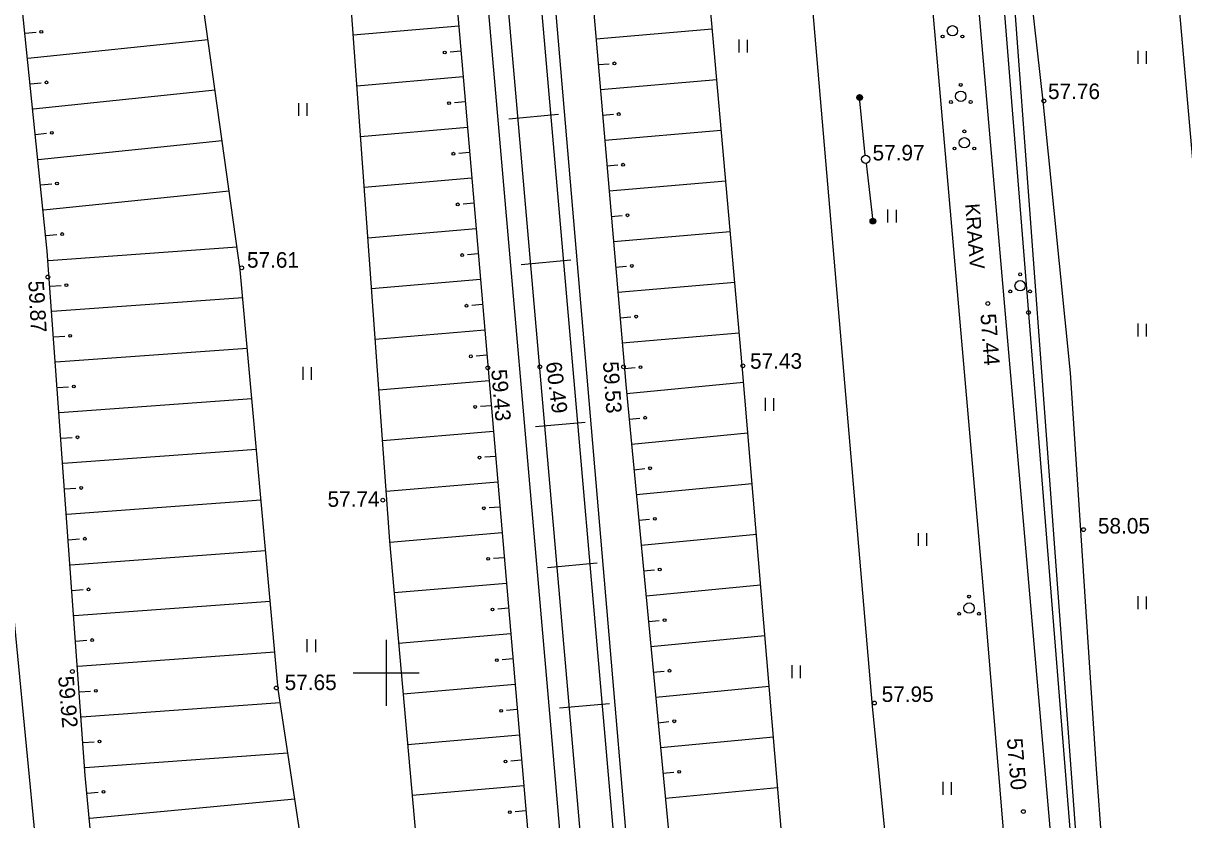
# Model space of a CAD drawing. Extents: x 9156 to 9809, y 2728 to 4000.
# Drawn here: x 9282.5 to 9338.5, y 3542.9 to 3581.3 of the extents above; entities that cross this region are included whole.
import ezdxf

# ---------------------------------------------------------------- set-up
doc = ezdxf.new("R2010")
doc.units = 0
for name, color, linetype in [('Level 1', 7, 'Continuous'), ('Level 54', 7, 'Continuous'), ('Level 58', 7, 'Continuous'), ('Level 6', 7, 'Continuous'), ('Level 7', 7, 'Continuous')]:
    doc.layers.add(name, color=color, linetype=linetype)

# ---------------------------------------------------------------- blocks, each defined once
blk = doc.blocks.new('KKOL')
at = {"layer": 'Level 58'}
for p, q in [((0, 1.59349), (0, -1.5935)), ((-1.5935, 0), (1.59349, 0))]:
    blk.add_line(p, q, dxfattribs=at)

msp = doc.modelspace()

# ---------------------------------------------------------------- linework, layer by layer
at = {"layer": 'Level 1'}
msp.add_line((9347.38, 3362.85), (9317.65, 3734.12), dxfattribs=at)
msp.add_line((9347.38, 3362.85), (9317.65, 3734.12), dxfattribs=at)
at = {"layer": 'Level 54'}
for p, q in [((9330.133, 3591.538), (9331.678, 3577.558)), ((9307.95, 3547.291), (9304.523, 3586.699)), ((9282.578, 3580.836), (9283.101, 3580.89)), ((9298.4, 3580.754), (9303.496, 3581.193)), ((9315.734, 3581.03), (9310.124, 3580.547)), ((9291.401, 3580.516), (9282.704, 3579.617)), ((9317.007, 3580.53), (9317.007, 3579.91)), ((9317.413, 3580.519), (9317.413, 3579.91)), ((9303.601, 3579.972), (9303.077, 3579.927)), ((9336.272, 3579.99), (9336.272, 3579.37)), ((9336.677, 3579.979), (9336.677, 3579.37)), ((9310.229, 3579.326), (9310.753, 3579.371)), ((9298.576, 3578.309), (9303.706, 3578.751)), ((9315.951, 3578.588), (9310.334, 3578.105)), ((9282.83, 3578.398), (9283.353, 3578.452)), ((9291.741, 3578.087), (9282.956, 3577.179)), ((9295.766, 3577.474), (9295.766, 3576.854)), ((9296.171, 3577.462), (9296.171, 3576.854)), ((9303.811, 3577.53), (9303.287, 3577.485)), ((9323.115, 3574.958), (9322.843, 3577.744)), ((9331.678, 3577.558), (9332.995, 3564.459)), ((9305.92, 3576.715), (9308.319, 3576.932)), ((9310.439, 3576.884), (9310.963, 3576.929)), ((9283.082, 3575.96), (9283.605, 3576.014)), ((9298.753, 3575.866), (9303.916, 3576.308)), ((9316.167, 3576.147), (9310.544, 3575.663)), ((9292.081, 3575.658), (9283.208, 3574.741)), ((9304.02, 3575.087), (9303.496, 3575.042)), ((9310.649, 3574.442), (9311.173, 3574.487)), ((9323.158, 3574.56), (9323.481, 3571.779)), ((9283.334, 3573.522), (9283.857, 3573.576)), ((9298.929, 3573.421), (9304.125, 3573.866)), ((9316.384, 3573.705), (9310.754, 3573.221)), ((9292.421, 3573.229), (9283.46, 3572.303)), ((9304.23, 3572.645), (9303.706, 3572.6)), ((9310.859, 3571.999), (9311.383, 3572.045)), ((9324.193, 3572.336), (9324.193, 3571.716)), ((9324.599, 3572.325), (9324.599, 3571.716)), ((9299.106, 3570.976), (9304.334, 3571.424)), ((9283.586, 3571.084), (9284.109, 3571.138)), ((9316.601, 3571.263), (9310.965, 3570.778)), ((9292.8, 3570.523), (9283.698, 3569.863)), ((9304.439, 3570.203), (9303.915, 3570.158)), ((9306.508, 3569.688), (9308.907, 3569.906)), ((9311.07, 3569.557), (9311.593, 3569.602)), ((9284.599, 3526.285), (9280.477, 3568.73)), ((9283.787, 3568.641), (9284.311, 3568.679)), ((9299.283, 3568.531), (9304.543, 3568.982)), ((9316.817, 3568.822), (9311.175, 3568.336)), ((9293.074, 3568.086), (9283.875, 3567.419)), ((9304.648, 3567.761), (9304.124, 3567.716)), ((9311.28, 3567.115), (9311.804, 3567.16)), ((9336.272, 3566.839), (9336.272, 3566.219)), ((9336.677, 3566.828), (9336.677, 3566.219)), ((9299.459, 3566.086), (9304.753, 3566.54)), ((9317.034, 3566.38), (9311.385, 3565.894)), ((9283.964, 3566.196), (9284.488, 3566.234)), ((9293.296, 3565.644), (9284.052, 3564.974)), ((9304.857, 3565.319), (9304.333, 3565.274)), ((9295.969, 3564.75), (9295.969, 3564.13)), ((9296.375, 3564.739), (9296.375, 3564.13)), ((9311.49, 3564.673), (9312.014, 3564.718)), ((9299.636, 3563.641), (9304.962, 3564.098)), ((9332.995, 3564.459), (9334.253, 3545.358)), ((9284.141, 3563.751), (9284.666, 3563.79)), ((9317.242, 3563.993), (9311.599, 3563.452)), ((9293.517, 3563.203), (9284.23, 3562.529)), ((9318.287, 3563.253), (9318.287, 3562.633)), ((9318.692, 3563.242), (9318.692, 3562.633)), ((9305.067, 3562.876), (9304.543, 3562.832)), ((9307.194, 3561.873), (9309.593, 3562.091)), ((9311.716, 3562.232), (9312.24, 3562.283)), ((9284.318, 3561.307), (9284.843, 3561.345)), ((9299.813, 3561.196), (9305.171, 3561.655)), ((9317.448, 3561.551), (9311.833, 3561.013)), ((9293.738, 3560.761), (9284.407, 3560.084)), ((9305.276, 3560.434), (9304.752, 3560.389)), ((9311.95, 3559.793), (9312.474, 3559.843)), ((9299.989, 3558.751), (9305.381, 3559.213)), ((9317.653, 3559.108), (9312.067, 3558.573)), ((9284.496, 3558.862), (9285.02, 3558.9)), ((9293.96, 3558.32), (9284.584, 3557.64)), ((9305.485, 3557.992), (9304.961, 3557.947)), ((9312.184, 3557.353), (9312.708, 3557.403)), ((9300.167, 3556.306), (9305.59, 3556.771)), ((9325.67, 3556.737), (9325.67, 3556.117)), ((9326.076, 3556.725), (9326.076, 3556.117)), ((9284.673, 3556.417), (9285.197, 3556.455)), ((9317.859, 3556.665), (9312.301, 3556.133)), ((9294.181, 3555.878), (9284.762, 3555.195)), ((9305.694, 3555.55), (9305.171, 3555.505)), ((9307.779, 3555.084), (9310.178, 3555.302)), ((9312.418, 3554.913), (9312.942, 3554.963)), ((9284.85, 3553.973), (9285.375, 3554.011)), ((9300.383, 3553.865), (9305.799, 3554.329)), ((9318.065, 3554.223), (9312.535, 3553.693)), ((9294.402, 3553.436), (9284.939, 3552.75)), ((9336.272, 3553.688), (9336.272, 3553.068)), ((9336.677, 3553.676), (9336.677, 3553.068)), ((9305.904, 3553.108), (9305.38, 3553.063)), ((9312.652, 3552.473), (9313.175, 3552.523)), ((9300.599, 3551.423), (9306.008, 3551.887)), ((9318.27, 3551.78), (9312.769, 3551.253)), ((9285.028, 3551.528), (9285.552, 3551.566)), ((9296.173, 3551.613), (9296.173, 3550.993)), ((9296.579, 3551.602), (9296.579, 3550.993)), ((9300, 3551.25), (9300, 3548.75)), ((9294.624, 3550.995), (9285.116, 3550.306)), ((9306.113, 3550.665), (9305.589, 3550.621)), ((9298.75, 3550), (9301.25, 3550)), ((9312.886, 3550.033), (9313.409, 3550.083)), ((9319.566, 3550.363), (9319.566, 3549.743)), ((9319.971, 3550.351), (9319.971, 3549.743)), ((9300.814, 3548.981), (9306.218, 3549.444)), ((9285.205, 3549.083), (9285.729, 3549.121)), ((9318.476, 3549.337), (9313.003, 3548.813)), ((9294.885, 3548.556), (9285.293, 3547.861)), ((9308.367, 3548.303), (9310.766, 3548.521)), ((9306.322, 3548.223), (9305.798, 3548.178)), ((9310.347, 3519.383), (9307.95, 3547.291)), ((9313.12, 3547.593), (9313.643, 3547.643)), ((9285.382, 3546.638), (9285.906, 3546.676)), ((9301.03, 3546.54), (9306.427, 3547.002)), ((9318.681, 3546.895), (9313.237, 3546.373)), ((9295.254, 3546.126), (9285.471, 3545.416)), ((9306.531, 3545.781), (9306.008, 3545.736)), ((9313.354, 3545.153), (9313.877, 3545.203)), ((9334.253, 3545.358), (9337.17, 3507.31)), ((9301.246, 3544.098), (9306.636, 3544.56)), ((9318.887, 3544.452), (9313.471, 3543.933)), ((9326.851, 3544.735), (9326.851, 3544.115)), ((9327.256, 3544.724), (9327.256, 3544.115)), ((9285.578, 3544.195), (9286.101, 3544.245)), ((9295.59, 3543.911), (9285.693, 3542.975)), ((9306.741, 3543.339), (9306.217, 3543.294))]:
    msp.add_line(p, q, dxfattribs=at)
for points in [[(9291.142, 3750), (9292.509, 3734.326), (9298.237, 3671.484), (9304.697, 3595.661), (9311.403, 3518.763), (9313.026, 3500)], [(9292.749, 3750), (9294.103, 3734.468), (9299.832, 3671.625), (9306.292, 3595.799), (9312.998, 3518.901), (9314.633, 3500)], [(9250, 3738.614), (9253.398, 3731.987), (9257.522, 3722.336), (9261.761, 3711.307), (9265.539, 3700.09), (9268.174, 3688.256), (9270.465, 3677.226), (9272.41, 3666.239), (9275.847, 3643.259), (9278.136, 3622.295), (9281, 3595.752), (9283.628, 3570.325), (9285.461, 3545.046), (9287.293, 3525.67), (9289.24, 3507.056), (9289.458, 3500)], [(9289.521, 3722.865), (9289.636, 3711.949), (9290.094, 3696.436), (9293.302, 3649.242), (9295.59, 3619.198), (9296.851, 3602.192), (9300.163, 3556.342), (9301.424, 3542.094), (9302.684, 3538.991), (9304.632, 3528.075), (9306.915, 3513.758), (9308.634, 3504.221), (9309.025, 3500)], [(9291.411, 3723.027), (9293.543, 3697.334), (9296.97, 3659.378), (9299.033, 3634.903), (9302.12, 3597.158), (9303.724, 3578.543), (9308.876, 3518.425), (9310.547, 3500)], [(9298.789, 3500), (9298.217, 3515.72), (9298.103, 3526.407), (9296.155, 3540.196), (9294.785, 3549.211), (9292.952, 3569.435), (9290.202, 3589.084), (9286.767, 3619.468), (9285.736, 3621.307), (9285.048, 3622.915), (9284.705, 3624.754), (9285.736, 3627.512), (9286.423, 3629.465), (9282.989, 3666.871), (9279.667, 3687.502), (9279.324, 3696.006), (9278.522, 3701.406), (9275.886, 3702.9), (9273.137, 3704.049)], [(9338.258, 3687.747), (9322.788, 3689.022), (9307.371, 3689.607), (9301.808, 3689.766), (9301.118, 3689.66), (9300.588, 3689.394), (9305.358, 3635.801), (9307.477, 3611.291), (9311.555, 3563.906), (9317.681, 3500)], [(9322.827, 3500), (9320.981, 3519.574), (9317.172, 3564.824), (9312.99, 3611.945), (9310.716, 3636.371), (9308.332, 3662.194), (9306.003, 3685.955), (9306.268, 3686.115), (9314.533, 3685.69)], [(9318.454, 3683.747), (9319.718, 3666.857), (9322.009, 3632.198), (9324.759, 3600.294), (9328.879, 3553.079), (9332.486, 3509.644), (9333.576, 3500)], [(9335.945, 3500), (9334.833, 3509.401), (9333.86, 3522.52), (9332.198, 3540.675), (9327.731, 3592.08), (9324.641, 3628.274), (9322.58, 3658.051), (9320.287, 3683.565)], [(9325.777, 3525.127), (9323.47, 3548.394), (9318.897, 3601.758), (9316.248, 3626.653)], [(9307.22, 3593.093), (9313.584, 3518.487), (9315.454, 3500)]]:
    msp.add_lwpolyline(points, dxfattribs=at)
for centre, radius in [((9283.356, 3580.909), 0.0683), ((9327.322, 3580.957), 0.25), ((9326.846, 3580.682), 0.0707), ((9327.799, 3580.682), 0.0707), ((9302.822, 3579.912), 0.0683), ((9311.008, 3579.385), 0.0683), ((9283.608, 3578.471), 0.0683), ((9327.723, 3577.797), 0.25), ((9327.723, 3578.347), 0.0707), ((9303.032, 3577.47), 0.0683), ((9322.843, 3577.744), 0.136), ((9322.843, 3577.744), 0.121), ((9322.843, 3577.744), 0.107), ((9322.843, 3577.744), 0.0902), ((9322.843, 3577.744), 0.0749), ((9322.843, 3577.744), 0.0616), ((9322.843, 3577.744), 0.0468), ((9322.843, 3577.744), 0.0343), ((9322.843, 3577.744), 0.0209), ((9322.843, 3577.744), 0.0112), ((9327.247, 3577.522), 0.0707), ((9328.2, 3577.522), 0.0707), ((9331.732, 3577.574), 0.0909), ((9311.218, 3576.943), 0.0683), ((9283.86, 3576.033), 0.0683), ((9327.895, 3575.556), 0.25), ((9327.895, 3576.106), 0.0707), ((9327.419, 3575.281), 0.0707), ((9328.372, 3575.281), 0.0707), ((9303.241, 3575.028), 0.0683), ((9323.135, 3574.759), 0.2), ((9323.135, 3574.759), 0.2), ((9311.428, 3574.501), 0.0683), ((9284.112, 3573.595), 0.0683), ((9303.45, 3572.586), 0.0683), ((9311.639, 3572.059), 0.0683), ((9323.481, 3571.779), 0.136), ((9323.481, 3571.779), 0.121), ((9323.481, 3571.779), 0.107), ((9323.481, 3571.779), 0.0902), ((9323.481, 3571.779), 0.0749), ((9323.481, 3571.779), 0.0616), ((9323.481, 3571.779), 0.0468), ((9323.481, 3571.779), 0.0343), ((9323.481, 3571.779), 0.0209), ((9323.481, 3571.779), 0.0112), ((9284.364, 3571.156), 0.0683), ((9303.66, 3570.144), 0.0683), ((9293.025, 3569.528), 0.0909), ((9311.849, 3569.617), 0.0683), ((9283.673, 3569.084), 0.0909), ((9330.588, 3569.212), 0.0707), ((9284.566, 3568.69), 0.0683), ((9330.588, 3568.662), 0.25), ((9330.111, 3568.387), 0.0707), ((9331.064, 3568.387), 0.0707), ((9303.869, 3567.702), 0.0683), ((9329.028, 3567.809), 0.0909), ((9330.991, 3567.37), 0.0909), ((9312.059, 3567.175), 0.0683), ((9284.744, 3566.245), 0.0683), ((9304.078, 3565.259), 0.0683), ((9304.903, 3564.704), 0.0909), ((9307.414, 3564.753), 0.0909), ((9311.45, 3564.753), 0.0909), ((9312.269, 3564.733), 0.0683), ((9317.209, 3564.803), 0.0909), ((9284.921, 3563.801), 0.0683), ((9304.288, 3562.817), 0.0683), ((9312.495, 3562.3), 0.0683), ((9285.098, 3561.356), 0.0683), ((9304.497, 3560.375), 0.0683), ((9312.729, 3559.86), 0.0683), ((9285.275, 3558.911), 0.0683), ((9299.836, 3558.322), 0.0909), ((9304.706, 3557.933), 0.0683), ((9312.963, 3557.42), 0.0683), ((9333.649, 3556.904), 0.0909), ((9285.453, 3556.466), 0.0683), ((9304.915, 3555.491), 0.0683), ((9313.197, 3554.98), 0.0683), ((9285.63, 3554.022), 0.0683), ((9328.122, 3553.123), 0.25), ((9328.122, 3553.673), 0.0707), ((9305.125, 3553.048), 0.0683), ((9327.646, 3552.848), 0.0707), ((9328.598, 3552.848), 0.0707), ((9313.431, 3552.54), 0.0683), ((9285.807, 3551.577), 0.0683), ((9305.334, 3550.606), 0.0683), ((9284.854, 3550.059), 0.0909), ((9313.664, 3550.1), 0.0683), ((9285.985, 3549.132), 0.0683), ((9294.699, 3549.269), 0.0909), ((9323.557, 3548.54), 0.0909), ((9305.543, 3548.164), 0.0683), ((9313.898, 3547.66), 0.0683), ((9286.162, 3546.687), 0.0683), ((9305.752, 3545.722), 0.0683), ((9314.132, 3545.22), 0.0683), ((9286.357, 3544.261), 0.0683), ((9305.962, 3543.28), 0.0683), ((9330.743, 3543.307), 0.0909)]:
    msp.add_circle(centre, radius, dxfattribs=at)
at = {"layer": 'Level 6'}
msp.add_line((9306.372, 3945.862), (9356.727, 3371.389), dxfattribs=at)
at = {"layer": 'Level 7'}
msp.add_line((9329.751, 3589.839), (9336.15, 3503.09), dxfattribs=at)

# ---------------------------------------------------------------- block references
at = {"layer": 'Level 54'}
msp.add_blockref('KKOL', (9300, 3550), dxfattribs=at)

# ---------------------------------------------------------------- texts
for s, p in [('57.76', (9331.932, 3577.665)), ('57.97', (9323.466, 3574.703)), ('57.61', (9293.28, 3569.533)), ('57.43', (9317.556, 3564.66)), ('57.74', (9297.167, 3558.002)), ('58.05', (9334.341, 3556.712)), ('57.65', (9295.099, 3549.165)), ('57.95', (9323.907, 3548.594))]:
    msp.add_text(s, height=0.75, dxfattribs=at).set_placement(p)
for s, height, rotation, p in [('KRAAV', 0.7, 274.5607, (9327.927, 3572.603)), ('59.87', 0.75, 273.2305, (9282.725, 3568.889)), ('57.44', 0.75, 274.386, (9328.669, 3567.292)), ('59.43', 0.75, 274.8652, (9305.064, 3564.605)), ('60.49', 0.75, 277.1786, (9307.699, 3564.954)), ('59.53', 0.75, 273.9339, (9310.453, 3564.99)), ('59.92', 0.75, 274.7447, (9284.169, 3549.816)), ('57.50', 0.75, 274.75, (9329.945, 3546.82))]:
    msp.add_text(s, height=height, rotation=rotation, dxfattribs=at).set_placement(p)

doc.saveas('drawing.dxf')
